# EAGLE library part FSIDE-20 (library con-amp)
AMP connector
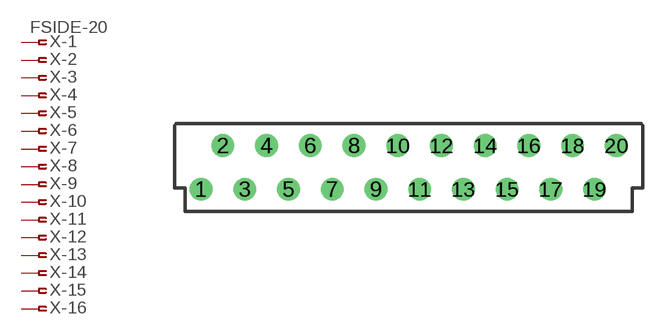
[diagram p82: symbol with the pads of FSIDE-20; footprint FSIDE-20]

Designator prefix X; gates -1=PIN-FV -2=PIN-F -3=PIN-F -4=PIN-F -5=PIN-F -6=PIN-F -7=PIN-F -8=PIN-F -9=PIN-F -10=PIN-F -11=PIN-F -12=PIN-F -13=PIN-F -14=PIN-F -15=PIN-F -16=PIN-F -17=PIN-F -18=PIN-F -19=PIN-F -20=PIN-F

## FSIDE-20 (OC_FARNELL: unknown; OC_NEWARK: unknown)  [FSIDE-20]
1  -1:1  pas
2  -2:1  pas
3  -3:1  pas
4  -4:1  pas
5  -5:1  pas
6  -6:1  pas
7  -7:1  pas
8  -8:1  pas
9  -9:1  pas
10  -10:1  pas
11  -11:1  pas
12  -12:1  pas
13  -13:1  pas
14  -14:1  pas
15  -15:1  pas
16  -16:1  pas
17  -17:1  pas
18  -18:1  pas
19  -19:1  pas
20  -20:1  pas

## Footprint FSIDE-20 (pad centres in mm)
AMP connector
drill 0.813 round: 1 -12.065,-1.27; 2 -10.795,1.27; 3 -9.525,-1.27; 4 -8.255,1.27; 5 -6.985,-1.27; 6 -5.715,1.27; 7 -4.445,-1.27; 8 -3.175,1.27; 9 -1.905,-1.27; 10 -0.635,1.27; 11 0.635,-1.27; 12 1.905,1.27; 13 3.175,-1.27; 14 4.445,1.27; 15 5.715,-1.27; 16 6.985,1.27; 17 8.255,-1.27; 18 9.525,1.27; 19 10.795,-1.27; 20 12.065,1.27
